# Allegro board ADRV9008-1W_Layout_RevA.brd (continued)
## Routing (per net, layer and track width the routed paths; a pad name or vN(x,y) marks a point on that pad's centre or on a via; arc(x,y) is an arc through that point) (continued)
VDD1P3_DIG: length 105.7
  TOP w0.203: R716.1 64.36,10.34 P904.1
  TOP w0.254: v4(37.24,35.68) U101.L9 v4(37.24,34.88) U101.L8 v4(37.24,34.08)
  TOP w0.508: R923.2 80.14,6.39 78.97,5.22 71.64,5.22 v2(70.65,6.21) v2(69.76,6.21) v2(68.87,6.21) v2(67.98,6.21) v2(67.98,6.97) v2(68.87,6.97) v2(69.76,6.97) v2(70.65,6.97)
  TOP w1.27: C951.1 68.02,9.57 P904.1
  L5_SIG w0.508: 64.04,9.57 P904.1 ; P904.1 65.12,8.49 ; P904.1 65.12,10.65 ; P904.1 66.2,9.57
  L5_SIG w1.905: 63.57,9.51 62.86,10.22 55.54,10.22 54.11,11.65 54.11,19.71 v2(52.42,21.4) v2(52.42,22.31) v2(53.47,22.31)
  L8_SIG w0.508: 65.12,8.49 P904.1 ; P904.1 66.2,9.57 ; P904.1 64.04,9.57 ; P904.1 65.12,10.65
  L12_PWR w0.635: v4(37.24,34.88) v4(37.24,35.68)
  L12_PWR w1.016: v4(37.24,34.88) v4(37.24,34.08) 38.25,33.07 40.27,33.07
  L12_PWR w1.27: 48.9,27.61 48.9,29.51 46.23,32.18 41.16,32.18 40.27,33.07
  L12_PWR w1.905: 48.9,27.61 50.17,26.34 50.17,24.8 52.66,22.31 ; 52.66,22.31 v2(52.42,22.31) v2(52.42,21.4) 53.46,21.4 v2(53.47,21.42) v2(53.47,22.31) 52.66,22.31
  BOTTOM w0.305: 37.24,34.46 v4(37.24,34.08) ; 37.24,34.46 v4(37.24,34.88) v4(37.24,35.68) 37.1,35.54 C643.1 ; 37.24,34.46 C642.1
  BOTTOM w0.508: 65.12,8.49 P904.1 ; P904.1 66.2,9.57 ; P904.1 64.04,9.57 ; P904.1 65.12,10.65
  BOTTOM w0.762: P904.1 64.99,9.44 C640.1
VDD_IF_LDO: length 2.9
  TOP w0.254: U902.5 57.63,1.99 58.1,2.46 58.1,3.62
  TOP w0.305: U902.7 56.66,3.36
VDD_INTERFACE: length 233.6
  TOP w0.203: R102.1 92.59,45.57 94.19,45.57 v2(94.81,44.94) ; U402.8 117.21,48.14 v2(117.49,47.87) ; v2(100.09,39.42) 100.09,39.42 C425.1
  TOP w0.254: U101.M12 v4(38.04,38.08)
  TOP w0.305: v2(122.74,53.6) U403.8 ; R104.1 93.34,36.75 98.32,36.75 100.09,38.52 v2(100.09,39.42) 100.09,39.99 R108.1 ; U902.2 51.35,3.29 51.03,3.61 ; R106.1 v2(94.81,44.94) ; U403.1 118.84,48.52 118.19,47.87 v2(117.49,47.87) ; v2(122.3,20.87) 122.11,21.06 U404.1 120.98,21.06 120.51,21.54 120.51,21.87 120.01,22.36 U404.4 ; v2(56.78,11.86) 55.25,13.39 R718.1 ; R832.1 R833.1 137.92,40.34 v4(137.83,40.26) ; R939.2 50.3,3.95 ; U902.1 51.41,3.94 51.01,4.35
  TOP w0.394: v4(132.75,12.32) 132.75,12.32 R111.1 ; P701.1 v2(60.2,66.02)
  TOP w0.508: P907.1 46.98,3.71 ; P907.1 48.06,2.63 ; P907.1 45.9,2.63 ; P907.1 46.98,1.55
  TOP w0.762: R938.2 131.45,9.75 v2(131.48,9.78)
  L3_PWR w0.508: v2(100.09,39.42) 100.09,41.5 100.21,41.62 100.21,42.15 99.83,42.52 99.47,42.52 97.05,44.94 97.05,45.23 96.52,45.76 95.64,45.76 v2(94.81,44.94)
  L3_PWR w0.635: 122.94,16.17 124.59,16.17 127.19,13.57 131.5,13.57 v4(132.75,12.32) 132.75,11.05 v2(131.48,9.78) ; 122.94,16.17 119.83,16.17 118.91,15.26 95.23,15.26 93.51,16.97 85.83,16.97 85.37,17.42 80.03,17.42 v2(78.75,18.71) 77.87,18.71 v2(77.86,18.72) v2(77.1,18.72) ; 122.94,16.17 122.94,20.23 v2(122.3,20.87)
  L12_PWR w0.203: 56.78,9.95 v2(56.78,11.86)
  L12_PWR w0.508: 115.2,40.43 115.2,46.78 116.28,47.87 v2(117.49,47.87) ; 125.36,40.18 125.36,47.16 123.83,48.69 123.83,52.5 v2(122.74,53.6) ; 45.9,2.63 P907.1 ; P907.1 46.98,1.55 ; P907.1 46.98,3.71 ; P907.1 48.06,2.63
  L12_PWR w0.762: 78.5,45 78.5,45.89 76.97,47.42 72.65,47.42 71.38,48.69 71.38,52.36 68.2,55.54 66.93,55.54 66.04,56.43 66.04,59.35 64.26,61.13 64.26,61.95 v2(60.2,66.02) ; 76.08,42.97 75.2,43.85 49.15,43.85 45.53,40.24 43.63,40.24 41.47,38.08 v4(38.04,38.08)
  BOTTOM w0.305: v4(38.04,38.08) 38.57,38.61 R110.1
  BOTTOM w0.394: C421.2 122.07,20.63 v2(122.3,20.87) 122.3,21.76 123.19,22.65 123.19,25.19 v2(121.54,26.84) ; P801.J39 v4(132.75,12.32) ; C423.2 122.81,53.53 v2(122.74,53.6) ; P801.K40 v2(131.48,9.78)
  BOTTOM w0.762: 46.47,3.14 46.45,3.14 46.45,3.16 ; 46.47,3.14 P907.1 ; 46.47,3.14 46.45,3.16 ; 46.45,3.16 C934.2
VDDA1P3_ANLG: length 67.3
  TOP w0.305: R726.1 v2(44.45,16.41)
  TOP w0.394: R916.2 83.03,20.04
  TOP w0.508: 63.98,15.46 P903.1 ; P903.1 65.06,16.54 ; P903.1 77.6,15.46 82.18,20.04 83.03,20.04 ; P903.1 65.06,14.38 ; 57.79,14.77 TP601.1 ; TP601.1 58.8,15.79 ; TP601.1 59.82,14.77 ; TP601.1 58.8,13.76
  TOP w0.762: C950.1 68.14,15.29 65.23,15.29 P903.1 64.35,16.17 C602.1
  L8_SIG w0.508: 63.98,15.46 P903.1 ; P903.1 65.06,14.38 ; P903.1 66.14,15.46 ; P903.1 65.06,16.54 ; TP601.1 59.82,14.77 ; TP601.1 57.79,14.77 ; TP601.1 58.8,13.76 ; TP601.1 58.8,15.79
  BOTTOM w0.394: R604.1 28.7,14.02 v6(28.71,14.01) ; R605.1 v2(45.85,18.33)
  BOTTOM w0.508: v2(7.5,29.5) 7.5,30.39 R607.1 ; P903.1 66.14,15.46 ; P903.1 65.06,14.38 ; P903.1 65.06,16.54 ; P903.1 63.98,15.46 ; R609.1 v2(7.24,19.6) ; TP601.1 59.82,14.77 ; TP601.1 57.79,14.77 ; TP601.1 58.8,15.79 ; TP601.1 58.8,13.76 ; R601.1 v2(41.53,15.91) v2(41.53,15.15)
  BOTTOM w0.762: 59.73,16.97 59.73,17.6 60.07,17.95 ; 21.59,57.44 20.84,57.44 R610.1 ; 21.59,57.44 21.6,57.44 v2(21.6,57.44) 21.59,57.44 ; 6.99,48.93 R608.1 ; R606.1 22.23,16.49
  BOTTOM w1.016: 19.59,61.66 v8(18.69,60.76) ; 19.59,61.66 19.59,61.66 v8(19.64,61.71) ; 19.59,61.66 E602.1 ; 8.38,48.93 6.99,48.93 ; 8.38,48.93 v8(9.65,48.93) ; 8.38,48.93 8.38,48.94 v8(8.32,48.94)
  BOTTOM w1.143: 22.23,16.49 22.25,16.48 22.25,15.62 22.23,15.61 v2(22.23,15.53)
  vias: v2(49.66,18.33) v2(50.33,18.33) v2(61.35,15.03) v2(61.35,14.27) v2(62.24,15.03) v2(62.24,14.27) v2(63.13,15.03) v2(63.13,14.27)
VDDA1P3_AUX_SYNTH: length 32.2
  TOP w0.254: U101.G8 v5(34.04,34.88)
  L12_PWR w0.279: v6(28.08,40.28) 28.39,40.28 28.83,39.84 28.83,39.8 28.84,39.79 28.84,39.51 29.07,39.28 29.4,39.28 29.4,39.28 29.47,39.28 29.85,38.9 29.85,38.01 30.99,36.87 32.61,36.87 32.84,36.64 32.84,36.31 33.07,36.08 33.36,36.08 33.38,36.07 33.4,36.07 33.63,35.84 33.63,35.82 33.64,35.8 33.64,35.27 v5(34.04,34.88)
  L12_PWR w0.508: v6(28.08,40.28) 22.35,53.76 TP612.1
  BOTTOM w0.305: C633.1 28.07,40.29
  BOTTOM w0.508: 27.94,40.87 27.94,40.42 v6(28.08,40.28) ; 27.94,40.87 28,40.81 C633.1 ; 27.94,40.87 C631.1
  BOTTOM w0.762: 20.7,56.19 20.7,56.18 20.69,56.17 20.65,55.18 ; 20.7,56.19 20.7,56.17 20.65,56.12 20.65,55.18 ; 20.7,56.19 R610.2 ; 20.65,55.18 20.65,54.85 TP612.1
VDDA1P3_AUX_VCO_LDO: length 28.3
  TOP w0.254: v5(30.04,35.68) U101.C10
  L12_PWR w0.508: v6(27.19,33.83) 26.81,33.83 25.82,32.84 25.1,32.84 22.53,30.27 v6(19.24,30.27)
  BOTTOM w0.203: 13.97,30.39 13.98,30.41 C623.1 ; 30.06,35.7 v5(30.04,35.68) ; C622.1 29.5,35.7
  BOTTOM w0.394: 30.06,35.7 28.27,35.7 27.64,35.07 27.64,34.28 v6(27.19,33.83)
  BOTTOM w0.508: 8.64,30.9 8.64,30.41 R607.2 8.63,31.97 TP609.1 8.64,30.9 ; 8.64,30.9 9.65,30.9 10.16,30.39 11.33,30.39 ; 11.33,30.39 19.12,30.39 v6(19.24,30.27) ; 11.33,30.39 C621.1
VDDA1P3_BB: length 21.1
  TOP w0.254: v4(31.64,31.68) U101.E5
  BOTTOM w0.203: v4(31.64,31.68) 31.5,31.82 C604.1
  BOTTOM w0.508: R601.2 41.4,18.06 41.4,19.69 C603.1 41.4,19.76 TP603.1 40.62,22.66 40.62,23.54 39.87,24.3 39.81,24.3 39.25,24.86 39.11,24.86 38.69,25.28 38.69,25.42 37.84,26.28 37.46,26.28 37.34,26.39 37.15,26.39 36.36,27.18 33.78,27.18 32.7,28.25 32.7,28.68 31.94,29.44 31.94,30.33 31.38,30.9 C605.1 31.25,31.29 v4(31.64,31.68)
VDDA1P3_CLOCK_SYNTH: length 21.2
  TOP w0.254: v5(34.04,31.68) U101.G5
  L12_PWR w0.394: TP607.1 45.85,22.56 43.86,24.55 42.67,24.55 41,26.23 39.13,26.23 38.83,25.93 37.87,25.93 36.89,26.91 36.89,29.46 36.21,30.14 35.69,30.14 34.15,31.68 v5(34.04,31.68)
  BOTTOM w0.394: R605.2 TP607.1
  BOTTOM w0.508: C617.1 33.98,31.62 v5(34.04,31.68) 33.97,31.74 C616.1
VDDA1P3_CLOCK_VCO_LDO: length 17.2
  TOP w0.254: v4(38.84,28.48) U101.N1
  BOTTOM w0.203: C611.1 38.67,28.65 v4(38.84,28.48)
  BOTTOM w0.508: R603.2 50.04,20.49
  BOTTOM w0.635: C610.1 40.8,27.82 40.25,28.37 C612.1 38.94,28.37 v4(38.84,28.48)
  BOTTOM w1.016: 50.04,20.49 TP605.1 47.5,24.42 47.5,25.69 45.21,27.98 42.42,27.98 42.26,27.82 C610.1
VDDA1P3_RF_LO: length 16.4
  TOP w0.254: v4(30.04,34.08) U101.C8
  L12_PWR w0.635: v4(30.04,34.08) 29.99,34.08 29.37,34.7 28.82,35.46
  L12_PWR w0.762: v6(17.27,39.69) v6(17.27,38.98) v6(17.27,38.27) 21.96,38.27 25.75,36.46 28.82,35.46
  BOTTOM w0.508: C627.1 29.97,34.01 v4(30.04,34.08)
VDDA1P3_RF_SYNTH: length 35.5
  TOP w0.254: v5(34.04,34.08) U101.G7
  L12_PWR w0.203: v7(25.53,60.49) v7(25.02,60.49)
  L12_PWR w0.279: v7(25.53,60.49) 25.53,58.46 29.36,54.63 29.36,50.99 28.95,50.58 28.95,45.24 29.09,45.11 29.09,43.98 28.74,43.64 28.74,42.53 29.34,41.93 29.34,40.55 30.36,39.54 31.37,39.54 33.13,37.78 33.78,37.78 33.87,37.68 34.22,37.68 35.26,36.65 35.26,34.75 35.01,34.5 34.46,34.5 v5(34.04,34.08)
  BOTTOM w0.203: v7(25.53,60.49) v7(25.02,60.49)
  BOTTOM w0.508: v5(34.04,34.08) 34.04,34.07 C609.1
VDDA1P3_RF_VCO_LDO: length 31.3
  TOP w0.254: U101.C5 v1(30.04,31.68) ; v4(30.04,32.48) U101.C6
  L3_PWR w0.508: v4(30.04,32.48) v1(30.04,31.68)
  L12_PWR w0.508: v6(25.66,31.29) 22.01,27.63 v6(19.18,27.63)
  BOTTOM w0.305: C628.1 15.15,26.36 15.13,26.37 ; 29.09,32.61 C629.1 30.03,32.49 v4(30.04,32.48)
  BOTTOM w0.394: 29.09,32.61 C630.1 27.68,32.61 27.56,32.49 26.86,32.49 v6(25.66,31.29)
  BOTTOM w0.508: v6(19.18,27.63) 16.39,27.63 13.78,25.02 13.78,21.44 12.7,20.36 TP611.1 12.19,19.85 11.09,18.75 10.37,18.75 9.53,19.6 R609.2
VDDA1P3_RX: length 11.2
  TOP w0.254: v4(30.04,30.88) U101.C3
  BOTTOM w0.394: v4(30.04,30.88) 30.04,30.2 30.29,29.95 C620.1 ; C618.1 24.25,18.68 24.25,18.67
  BOTTOM w0.762: R606.2 23.28,17.7
  BOTTOM w1.143: v6(26.93,25.95) TP608.1 26.4,22.79 24.25,18.67 23.28,17.7
VDDA1P3_RX_RF: length 8.4
  TOP w0.254: U101.B1 v4(29.24,28.48)
  L12_PWR w0.394: v6(28.71,23.03) 28.1,23.64 28.1,24.2 28.71,24.81 v7(28.71,26.06)
  BOTTOM w0.305: 29.23,28.47 v4(29.24,28.48) 29.5,28.74 C615.1
  BOTTOM w0.394: R612.2 28.7,23.03 v6(28.71,23.03) ; 28.71,26.71 28.71,27.52 28.91,27.71 28.91,28.14 29.23,28.47 ; 28.71,26.71 C613.1 ; 28.71,26.71 v7(28.71,26.06)
  BOTTOM w0.508: C614.1 28.92,27.73 28.91,27.71
VDDA1P3_SER: length 38.1
  TOP w0.203: v1(38.84,38.08) U101.N12 ; v1(38.84,36.48) U101.N10 ; U101.P12 v1(39.58,38.01) ; v1(39.63,38.94) 39.63,38.87 U101.P13 ; U101.M13 v1(38.04,38.88) ; U101.M14 v1(37.24,38.88) ; v1(38.84,38.88) U101.N13 ; U101.P11 v1(39.62,37.35) ; v1(38.84,37.28) U101.N11 ; v1(39.64,39.68) U101.P14
  TOP w0.254: v4(39.64,35.68) U101.P9 ; U101.L13 v5(36.44,38.88) ; v4(39.64,34.08) U101.P8 v4(38.84,34.08) U101.N8 ; U101.L14 v5(37.24,39.68) ; v4(38.84,35.68) U101.N9
  BOTTOM w0.203: 40.2,33.8 40.2,33.81 C634.1
  BOTTOM w0.394: 40.2,32.89 40.2,32.86 C635.1
  BOTTOM w0.508: C635.1 40.28,32.81 ; 40.28,32.81 40.2,32.89 40.2,33.8 39.93,34.08 v4(39.64,34.08) v4(38.84,34.08) ; 40.28,32.81 40.92,32.17 46.23,32.17 48.64,29.76 50.69,29.76 51.36,29.09 53.9,29.09 56.52,26.47 56.52,23.11 56.52,23.1 TP613.1
  BOTTOM w1.016: E611.2 TP613.1
VDDA1P8_AN: length 20.1
  TOP w0.203: U101.E12 v1(31.64,38.08)
  TOP w0.279: C947.1 v3(26.48,41.06)
  TOP w0.305: v3(26.48,41.06) 26.3,40.88 C948.1
  TOP w0.394: v2(47.37,17.18) 47.39,17.17 R724.1
  TOP w0.508: 99.19,3.72 TP901.1 ; TP901.1 101.22,3.72 ; TP901.1 100.21,2.71 ; TP901.1 100.21,4.74
  L3_PWR w0.203: 30.45,39.06 30.45,39.25 30.67,39.25 30.68,39.26 31,39.26 31.26,39 31.26,38.72 31.64,38.34 v1(31.64,38.08) 31.38,38.08 31,38.46 30.72,38.46 30.46,38.72 30.46,39.03 30.47,39.04 30.45,39.06
  L3_PWR w0.394: 46.74,16.68 46.87,16.68 v2(47.37,17.18)
  L3_PWR w0.508: TP901.1 100.21,4.74 ; TP901.1 101.22,3.72 ; TP901.1 100.21,2.71 ; TP901.1 99.19,3.72 ; v3(26.48,41.06) 28.64,41.06 30.45,39.25
  vias: v2(101.6,4.74) v2(101.86,3.72)
VDDA1P8_BB: length 67.4
  TOP w0.254: v5(32.44,30.88) U101.E4
  TOP w0.394: R722.1 v2(49.47,17.18)
  L5_SIG w0.114: TP903.1 26.55,8.8 27.82,8.8 29.59,10.58 31.37,10.58 31.63,10.33 33.91,10.33 34.67,11.09 40.64,11.09 41.02,10.71 43.69,10.71 49.47,16.49 v2(49.47,17.18)
  L10_SIG w0.279: v5(32.44,30.88) 32.04,30.48 31.49,30.48 31.24,30.24 31.24,29.1 30.94,28.8
  L10_SIG w0.305: 30.94,28.8 30.5,28.8
  L10_SIG w0.394: 29.83,27.62 29.83,28.12 30.5,28.8
  L10_SIG w0.508: 25.02,8.04 25.02,15.28 26.86,17.12 26.86,18.52 28.44,20.1 28.44,23.29 27.94,23.79 27.94,25.73 29.83,27.62
  L10_SIG w0.762: TP903.1 25.02,7.28 25.02,8.04
  BOTTOM w0.305: C944.1 32.51,30.95 v5(32.44,30.88) ; 25.61,5.75 R942.2
  BOTTOM w0.508: C945.1 32.58,30.73 v5(32.44,30.88)
  BOTTOM w1.016: 25.61,5.75 25.02,5.75 24.35,6.43 ; 24.35,6.43 C943.1 ; 24.35,6.43 TP903.1 24.26,8.55 C942.1
VDDA_1P8: length 113.1
  TOP w0.508: R931.2 102.34,6.62 v2(103.38,5.58) v2(104.14,5.58) v2(104.9,5.58) ; P906.1 107.64,4.74 ; P906.1 105.48,4.74 ; P906.1 106.56,3.66 ; P906.1 106.56,5.82
  BOTTOM w0.305: 27.05,5.75 R942.1 ; C940.2 105.54,3.72 P906.1 107.7,3.6 C941.2
  BOTTOM w0.508: P906.1 107.64,4.74 ; P906.1 105.48,4.74 ; P906.1 106.56,3.66 ; P906.1 106.56,5.82
  BOTTOM w1.016: 104.14,2.83 102.49,1.18 61.09,1.18 59.82,2.45 58.04,2.45 54.23,6.26 42.42,6.26 39.88,8.8 38.48,8.8 34.67,12.61 30.23,12.61 28.7,11.09 28.7,6.52 27.94,5.75 27.05,5.75
VDDA_3P3: length 139.8
  TOP w0.254: U101.C12 v1(30.04,38.08)
  TOP w0.394: v4(133.42,62.28) R848.1 ; R720.1 v3(51.56,17.18)
  TOP w0.508: R935.1 103.04,17.69 v2(103.04,19.29) v2(102.27,19.29) v2(101.51,19.29) 99.61,19.29 98.73,20.17 R927.2
  L3_PWR w0.203: 31.22,37.43 31.22,37.12 31.21,37.11 31.21,36.89 31.02,36.89 31.01,36.9 31,36.89 30.68,36.89 30.42,37.16 30.42,37.44 30.04,37.82 v1(30.04,38.08) 30.29,38.08 30.67,37.69 30.96,37.69 31.22,37.43
  L3_PWR w0.508: 45.72,58.71 47.75,58.71 49.15,57.32 51.82,57.32 v2(52.2,57.7) ; 45.72,58.71 45.72,59.86 44.33,61.25 v2(44.33,62.14) ; 45.72,58.71 43.44,58.71 v2(41.53,60.62) ; 45.72,58.71 45.72,56.3 ; 103.37,20.34 P905.1 ; P905.1 103.37,22.5 ; P905.1 104.45,21.42 ; P905.1 102.29,21.42 ; 34.04,39.66 32.51,38.14 32.51,37.38 31.88,36.74 31.36,36.74 31.21,36.89
  L10_SIG w0.203: 59.06,10.71 57.02,12.75 56,12.75 v3(51.56,17.18)
  L12_PWR w0.394: v4(133.42,62.28) 134.87,62.28 139.76,57.39 139.76,54.48 140.99,53.25 140.99,32.06 138.36,29.43 136.31,29.43 134.63,27.75 134.63,27.31 134.27,26.96 133.84,26.96 129.57,22.69 122.27,22.69 120.53,24.43 115.07,24.43 114.46,23.82 111.28,23.82 106.76,19.29 v2(103.04,19.29) v2(102.27,19.29) v2(101.51,19.29)
  BOTTOM w0.305: R119.1 v2(41.53,60.62) ; v2(52.2,57.7) 52.39,57.89 R120.1 ; C135.1 v2(44.33,62.14)
  BOTTOM w0.508: P905.1 103.37,22.5 ; P905.1 103.37,20.34 ; P905.1 102.29,21.42 ; P905.1 104.45,21.42 ; 44.33,61.32 v2(44.33,62.14)
  vias: v2(57.41,8.68) v2(58.43,8.68) v2(58.47,7.41) v2(58.94,8.05) v2(59.45,8.68) v2(59.45,7.41)
1P3_BUCK_OUT: length 25.4
  L8_SIG w0.394: v2(77.64,6.69) v2(76.87,6.69) v2(76.11,6.69) 75.41,7.4 75.41,18.42 77.23,20.24 84.4,20.24 v2(85.18,21.02)
  BOTTOM w0.394: v2(85.18,21.02) 85.59,20.61 R905.1
3P3V_CLK1: length 38.3
  TOP w0.203: v2(107.63,66.77) 107.12,66.77 C440.2 ; U404.6 119.82,20.88 v2(119.82,20.13)
  TOP w0.305: C424.2 117.74,55.17 v2(118.11,55.54) 118.53,55.54 118.84,55.23 U403.14
  TOP w0.394: v2(87.54,65.06) 87.38,64.9 87.38,64.86 C438.2 ; C442.2 85.71,61.57 v2(85.14,62.14) ; C439.2 86.31,64.8 v2(86.04,65.06) ; v2(88.87,56.77) 88.87,57.43 C427.2 ; v2(95.34,56.63) C429.2 ; v2(93.44,59.63) 92.84,59.03 C431.2 ; C428.2 v2(93.54,54.83) ; v2(85.14,60.63) 85.47,60.3 C418.1 ; C433.2 92.97,62.63 v2(93.45,62.63) ; C436.2 90.27,64.8 v2(90.54,65.06) ; C437.2 88.77,64.8 v2(89.04,65.06) ; C426.1 86.11,57.39 v2(86.11,56.73) ; v2(92.04,65.06) 91.77,64.8 C435.2 ; v2(93.41,66.78) 93.41,67.17 C434.2 ; v2(85.14,63.63) 85.93,62.84 C443.2 ; C444.2 v2(83.24,65.13) ; C441.2 83.31,57.16 v2(83.2,57.05) ; v2(93.42,61.13) 92.76,60.47 C432.2 ; C430.2 93.07,57.76 v2(93.44,58.13)
  BOTTOM w0.203: U401.69 v2(93.44,58.13) ; U401.66 v2(93.44,59.63) ; U401.39 v2(86.04,65.06) ; 94.24,56.63 U401.72 ; U401.1 v2(93.54,54.83) ; v2(86.11,56.73) 86.04,56.73 U401.16 ; U405.5 v2(107.63,66.77) ; 89.04,55.93 U401.10 ; 92.04,65.07 U401.51 ; U401.48 v2(90.54,65.06)
  BOTTOM w0.254: U401.60 v2(93.45,62.63) ; v2(93.42,61.13) 93.42,61.13 93.42,61.13 93.42,61.13 U401.63 ; 89.04,55.93 89.04,56.54 88.84,56.75 88.84,56.85 88.87,56.85 v2(88.87,56.77) ; U401.33 v2(85.14,63.63) ; v2(85.14,62.14) 85.03,62.14 85.03,62.08 84.98,62.13 U401.30 ; U401.45 v2(89.04,65.06) ; v2(93.41,66.78) 93.41,66.91 93.54,66.78 U401.54 ; U401.36 v2(83.24,65.13) ; v2(92.04,65.06) 92.04,65.07 ; v2(95.34,56.63) 94.24,56.63 ; U401.27 v2(85.14,60.63) ; U401.20 83.82,57.13 83.8,57.11 83.72,57.11 83.66,57.05 v2(83.2,57.05) ; U401.42 v2(87.54,65.06)
  BOTTOM w0.394: C422.2 v2(119.82,20.13) ; v2(83.2,57.05) 82.98,56.83 R440.1
  vias: v2(109.99,19.03) v2(109.99,18.27) v2(110.88,19.03) v2(110.88,18.27) v2(111.77,19.03) v2(111.77,18.27)
3P3V_VCXO: length 64.1
  BOTTOM w0.305: C938.2 127.01,62.26 127.01,62.27
  BOTTOM w0.394: C407.2 v2(111,63.8) Y402.6 Y401.6
  BOTTOM w0.508: E906.2 103.91,25.59 107.97,25.59 109.86,27.48 111.13,27.48 114.18,30.53 116.21,30.53 118.75,33.07 120.53,33.07 126.5,39.04 126.97,39.04 130.06,42.13 130.06,59.74 127.53,62.27 v2(126.23,62.27) v2(125.56,62.27) 125.56,61.43 124.82,60.69 124.35,60.21 R408.1
3P3VAUX: length 104.4
  TOP w0.305: 126.61,19.28 125.11,19.28 ; 126.61,19.28 C703.1 ; 126.61,19.28 127.66,19.28 v2(127.68,19.26) ; 125.11,19.28 123.44,19.28 U702.8 ; 125.11,19.28 C704.1 ; U703.10 v2(45.49,9.59) ; v2(112.97,20.97) 113.21,20.73 R708.2 ; U703.17 U703.16 ; R709.2 v2(113.8,17.83) ; R710.2 v2(113.8,16.05)
  TOP w0.635: U703.16 50.55,9.59 51.2,8.94 v8(51.2,7.67)
  L10_SIG w0.394: v2(45.49,9.59) 46.4,8.68 50.18,8.68 v8(51.2,7.67)
  L10_SIG w0.762: v2(112.97,20.97) 113.8,20.13 v2(113.8,17.83) v2(113.8,16.05) 113.8,4.75 110.12,1.06 107.45,1.06 107.15,0.76 105.96,0.76 105.66,1.06 61.6,1.06 59.19,3.48 57.03,3.48 52.84,7.67 v8(51.2,7.67)
  BOTTOM w0.394: C701.2 50.22,8.37 50.91,7.67 v8(51.2,7.67) 51.19,7.68 C702.1 ; P801.D32 v4(139.1,21.21)
ADP5054_VREG: length 20.4
  TOP w0.394: R903.2 87.86,8.29 v2(88.25,8.68) 88.95,9.38 90.64,9.38 91.04,8.98 91.04,8.83 v2(91.07,8.8) 91.4,9.13 91.4,16.32 v2(89.62,18.1)
  BOTTOM w0.203: C902.2 89.7,18.17 v2(89.62,18.1) 89.03,17.5 ; U901.44 88.75,17.22 89.03,17.5 ; U901.45 89.25,17.28 89.03,17.5
  BOTTOM w0.254: U901.13 90.75,9.12 v2(91.07,8.8) ; U901.18 v2(88.25,8.68)
AUX_SYNTH_VTUNE: length 49.1
  TOP w0.203: J101.1 56.39,35.98 P104.6
  TOP w0.254: v1(39.64,28.48) U101.P1
  L5_SIG w0.114: v1(39.64,28.48) 39.25,28.86 37.33,28.86 36.58,29.61 36.34,29.61 35.17,30.78 35.17,31.02 34.91,31.28 34.76,31.28 34.5,31.54 34.5,39.05 34.74,39.28 34.74,42.39 36.25,43.91 36.68,43.91 36.98,44.21 36.98,44.64 37.91,45.57 44.42,45.57 44.68,45.31 45.27,45.31 45.85,45.89 51.31,45.89 55.12,42.08 55.12,40.11 P104.6
AUXADC_0: length 64.3
  TOP w0.254: U101.F3 v1(32.44,30.08)
  L8_SIG w0.114: v1(32.44,30.08) 32.1,30.41 32.1,32.46 32.77,33.14 32.77,33.32 33.15,33.69 33.33,33.69 33.65,34.01 33.65,34.24 33.9,34.49 34.2,34.49 34.5,34.79 34.5,35.06 34.78,35.34 34.98,35.34 35.3,35.66 35.3,36.62 35.5,36.81 35.78,36.81 36.1,37.14 36.1,37.42 36.3,37.61 38.85,37.61 39.24,38 39.24,38.15 39.44,38.35 39.72,38.35 39.8,38.27 40.98,38.27 43.28,40.56 44.74,40.56 48.92,44.74 68.8,44.74 72.35,48.3 79.19,48.3 79.89,49 79.89,50.97 P103.3
  BOTTOM w0.203: C131.1 81.09,52.3 P103.3
AUXADC_1: length 66.8
  TOP w0.254: U101.F4 v1(32.44,31.68)
  L7_SIG w0.114: v1(32.44,31.68) 32.44,32 32.1,32.34 32.1,33.29 31.65,33.74 31.5,33.74 31.24,33.99 31.24,34.95 30.98,35.21 30.79,35.21 30.48,35.52 30.48,38.2 30.83,38.54 30.98,38.54 31.17,38.74 31.17,38.89 31.63,39.34 31.78,39.34 31.97,39.54 31.97,39.69 32.2,39.92 32.3,40.01 32.72,40.01 32.83,40.13 32.83,41.63 36.32,45.12 37.47,45.12 40.77,48.43 46.74,48.43 47.69,47.47 63.63,47.47 64.65,48.49 79.95,48.49 81.16,49.7
  BOTTOM w0.203: 81.16,49.7 81.09,49.63 C132.1
AUXADC_2: length 84.2
  TOP w0.254: v1(32.44,36.48) U101.F11
  L5_SIG w0.114: P103.5 76.27,54.58 76.24,54.58 75.94,54.88 75.94,54.91 74.55,56.3 66.04,56.3 62.42,59.92 39.69,59.92 38.1,58.33 30.23,58.33 28.58,56.68 27.56,56.68 25.91,55.03 25.91,51.14 26.59,50.46 26.59,49.42 25.08,47.92 25.08,45.89 25.88,45.09 25.88,40.16 29.23,36.81 32.1,36.81 v1(32.44,36.48)
  BOTTOM w0.203: C133.1 78.55,52.3 P103.5
AUXADC_3: length 82.2
  TOP w0.203: U101.E11 v1(31.64,37.28)
  L5_SIG w0.114: 78.62,49.7 77.35,50.97 77.35,52.68 76.08,53.95 66.24,53.95 61.03,59.16 39.94,59.16 38.48,57.69 36.23,57.69 35.72,57.19 29.93,57.19 28.82,56.09 27.73,56.09 26.5,54.86 26.5,51.39 27.18,50.71 27.18,49.03 25.78,47.63 25.78,46.18 26.93,45.03 26.93,42.21 27.08,42.05 28.51,40.62 28.51,40.17 28.83,39.85 28.83,39.61 29.15,39.28 29.31,39.28 29.57,39.02 29.57,38.79 29.96,38.41 30.18,38.41 30.5,38.09 30.5,37.94 30.74,37.7 31.22,37.7 v1(31.64,37.28)
  BOTTOM w0.203: C134.1 78.55,49.63 78.62,49.7
CLK+: length 7.5
  BOTTOM w0.203: C403.2 93.54,50.77 92.72,50.77 ; 92.72,50.77 92.28,50.77 92.06,50.99 92.06,51.72 92.97,52.62 92.97,55.06 93.04,55.13 U401.2 ; 92.72,50.77 R406.1
CLK-: length 8.1
  BOTTOM w0.203: C405.2 93.54,50.42 92.72,50.42 ; R406.2 92.72,50.42 ; 92.72,50.42 92.13,50.42 91.7,50.85 91.7,51.86 92.61,52.77 92.61,55.06 92.54,55.13 U401.3
CLK_RESETB: length 109.9
  TOP w0.203: v2(120.18,22.92) 119.33,22.92 119.1,22.68 119.1,22.04 119.43,21.71 U404.5
  L7_SIG w0.114: v2(120.18,22.92) 120.75,22.35 121.29,22.35 121.3,22.35 130.27,22.35 131,23.09 134.02,23.09 134.83,23.9 134.83,23.94 135.44,24.56 135.49,24.56 135.76,24.83 135.76,24.87 136.81,25.92 136.86,25.92 137.1,26.16 137.1,26.21 137.64,26.75 137.69,26.75 138.87,27.94 138.87,28.55 142.25,31.92 142.25,46.91 141.94,47.22 137.82,47.22 137.68,47.07 134.72,47.07 132.09,49.7 127.39,49.7 125.23,51.86 105.79,51.86 105.28,51.35 93.8,51.35 92.59,52.55 86.97,52.55 86.9,52.62 86.87,52.62 83.45,56.03 v2(83.45,56.36)
  BOTTOM w0.203: U401.19 83.72,56.63 v2(83.45,56.36)
  BOTTOM w0.394: v2(83.45,56.36) 82.93,55.84 R440.2
CLK_SYSREF_REQUEST: length 36.4
  TOP w0.203: U403.13 v2(119.49,56.68)
  L7_SIG w0.114: v2(119.49,56.68) 118.05,56.68 117.67,57.06 109.6,57.06 109.22,56.68 100.46,56.68 97.73,59.41 v2(97.73,65.95)
  BOTTOM w0.254: v2(97.73,65.95) 96.65,64.87 96.27,64.87 95.53,64.13 U401.57 ; R441.2 97.73,66.59
  BOTTOM w0.394: 97.73,66.59 v2(97.73,65.95)
DIR_CLK+: length 12.7
  L10_SIG w0.091: v2(89.35,51.41) 88.65,51.41 88.42,51.18 88.42,50.06 88.51,49.96 90.84,49.96 91.34,50.47 95.3,50.47 95.63,50.79 v2(95.63,52.09)
  BOTTOM w0.203: C402.2 94.88,52.09 v2(95.63,52.09) ; R416.2 89.78,50.85 89.35,51.28 v2(89.35,51.41)
DIR_CLK-: length 12.8
  L10_SIG w0.091: v2(95.63,49.09) 95.63,49.95 95.36,50.21 91.45,50.21 90.95,49.71 88.4,49.71 88.16,49.95 88.16,51.14 87.89,51.41 v2(87.12,51.41)
  BOTTOM w0.203: v2(87.12,51.41) 87.12,51.16 86.76,50.79 R415.2 ; v2(95.63,49.09) 94.88,49.09 94.87,49.08 C404.2
EPROM_A0: length 115.9
  TOP w0.203: U703.11 47.52,8.19 v2(46.87,7.54)
  TOP w0.305: v2(119.89,18.21) 118.85,19.25 U702.1 116.61,19.25 115.77,20.09 R711.2 R708.1
  L8_SIG w0.114: v2(119.89,18.21) 119.39,18.21 114.31,13.13 102.5,13.13 94.18,4.81 84.65,4.81 83.58,3.73 57.67,3.73 52.34,9.06 48.39,9.06 v2(46.87,7.54)
  L10_SIG w0.114: v2(119.89,18.21) 124.08,14.02 136.53,14.02 137.37,14.85 137.37,15.05 139.72,17.4 v4(141.64,17.4)
  BOTTOM w0.394: P801.C34 v4(141.64,17.4)
EPROM_A1: length 115.8
  TOP w0.203: U703.13 48.52,7.92 v2(48.14,7.54)
  TOP w0.305: v2(118.85,18.39) 118.64,18.6 U702.2 116.46,18.6 116.11,18.95 R712.2 R709.1
  L8_SIG w0.114: v2(48.14,7.54) 49.14,8.54 52.09,8.54 57.61,3.03 95.7,3.03 97.67,4.99 99.19,4.99 105.8,11.6 114.06,11.6 120.46,18.01 120.46,18.41 120.02,18.84 119.26,18.84 118.85,18.43 v2(118.85,18.39)
  L10_SIG w0.114: v2(118.85,18.39) 123.98,13.25 137.5,13.25 v4(140.37,16.13)
  BOTTOM w0.394: P801.D35 v4(140.37,16.13)
EPROM_A2: length 4.1
  TOP w0.305: R710.1 R713.2 115.63,17.17 115.97,17.51 116.07,17.51 116.5,17.95 U702.3
FMC_CLK_RESETB: length 24.7
  TOP w0.305: U404.2 122.77,21.71 123.77,22.71 128.97,22.71 129.86,21.82 135.57,21.82 138.57,24.82 138.57,27.03 v4(140.37,28.83)
  BOTTOM w0.394: v4(140.37,28.83) P801.D26
FMC_SYSREF_REQUEST: length 46.4
  TOP w0.203: U403.2 v2(119.49,50.59)
  L8_SIG w0.114: v2(119.49,50.59) 121.74,48.33 125.84,48.33 126.86,49.35 129.4,49.35 132.77,45.97 139.13,45.97 141.18,43.92 141.18,43.88 142.25,42.81 142.25,36.37 141.16,35.29 141.16,31.4 141.16,31.4 141.16,30.93 141.16,30.93 141.16,27.08 v4(140.37,26.29)
  BOTTOM w0.394: v4(140.37,26.29) P801.D27
FMCA_SCL: length 107
  TOP w0.203: U703.15 49.52,8.06 v2(50.05,7.54)
  TOP w0.305: U702.6 122.19,17.95 v2(121.8,18.33)
  L8_SIG w0.114: v2(50.05,7.54) 51.57,6.02 53.73,6.02 57.41,2.33 95.37,2.33 95.76,1.94 102.24,1.94 103.63,3.34 107.95,3.34 113.54,8.93 113.54,9.82 120.91,17.19 120.91,17.45 v2(121.8,18.33)
  L10_SIG w0.114: v4(141.64,22.48) 141.06,21.89 133.87,21.89 130.69,18.71 122.68,18.71 122.31,18.33 v2(121.8,18.33)
  BOTTOM w0.394: v4(141.64,22.48) P801.C30
FMCA_SDA: length 110.4
  TOP w0.203: U703.14 v2(49.02,7.54)
  TOP w0.305: U702.5 v2(121.82,17.3)
  L8_SIG w0.114: v2(49.02,7.54) 49.02,6.15 53.6,1.57 95,1.57 95.77,0.8 107.44,0.8 114.68,8.04 114.68,10.07 121.82,17.21 v2(121.82,17.3)
  L10_SIG w0.114: v2(121.82,17.3) 123.98,17.3 125.1,16.18 126.88,16.18 127.52,16.81 137.3,16.81 141.64,21.16 v4(141.64,21.21)
  BOTTOM w0.394: v4(141.64,21.21) P801.C31
FMCA_VADJ: length 13.2
  TOP w0.762: TP814.1 129.45,6.74 131.44,6.74 ; R938.1 131.44,6.74 ; 131.44,6.74 131.45,6.73 C932.1
  L12_PWR w0.508: TP814.1 129.31,7.89 ; TP814.1 128.3,6.87 ; TP814.1 127.28,7.89 ; TP814.1 128.3,8.91
  BOTTOM w0.394: P801.E39 v4(139.1,11.05) ; P801.G39 v4(136.56,11.05) ; P801.H40 v4(134.02,11.05) ; P801.F40 v4(137.83,9.78)
FMCA_VCC_3P3V: length 7.7
  L12_PWR w0.508: TP818.1 128.37,12.21 ; TP818.1 129.39,11.19 ; TP818.1 127.36,11.19 ; TP818.1 128.37,10.17
  BOTTOM w0.394: P801.D38 v4(140.37,12.32) ; P801.C39 v4(141.64,11.05) ; P801.D40 v4(140.37,9.78) ; P801.D36 v4(140.37,14.86)
FMCA_VCC_12P0V: length 5.9
  TOP w0.508: 121.29,12.87 TP819.1 ; TP819.1 121.29,14.91 ; TP819.1 120.28,13.89 ; TP819.1 122.31,13.89
  BOTTOM w0.394: P801.C35 v4(141.64,16.13) ; P801.C37 v4(141.64,13.59)
FPGA_REF_CLK+: length 49
  TOP w0.203: C803.1 141.01,56.26 140.5,56.77 v4(140.37,56.77)
  L7_SIG w0.091: v4(140.37,56.77) 140.25,56.77 139.99,57.03 139.99,57.41 132.84,64.56 127.36,64.56 126.22,65.7 110.26,65.7 109.45,64.89 108.33,64.89 v2(108.05,65.17)
  BOTTOM w0.203: v2(108.05,65.17) 107.82,64.94 106.43,64.94 102.03,60.53 99.72,60.53 99.59,60.54 99.25,60.88 98.85,60.88 R420.2
FPGA_REF_CLK-: length 49
  TOP w0.203: v4(139.1,56.77) 138.78,56.77 138.5,56.49 C804.1
  L7_SIG w0.091: v4(139.1,56.77) 139.65,56.77 139.74,56.86 139.74,57.3 132.74,64.3 127.26,64.3 126.11,65.44 110.37,65.44 109.55,64.63 108.33,64.63 v2(108.05,64.36)
  BOTTOM w0.203: R419.2 99.25,59.85 99.58,60.18 99.72,60.18 102.17,60.18 106.58,64.58 107.82,64.58 v2(108.05,64.36)
FPGA_SYSREF+: length 44.5
  TOP w0.203: v4(135.29,55.5) 134.86,55.07 134.86,54.66 135.13,54.66 135.13,54.25 134.86,54.25 134.86,53.01 135.06,52.81 R818.1
  L7_SIG w0.091: v2(99.68,63.79) 99.96,63.51 101.12,63.51 103.25,61.38 129.8,61.38 134.81,56.36 134.81,55.73 135.04,55.5 v4(135.29,55.5)
  BOTTOM w0.203: v2(99.68,63.79) 99.45,63.56 99.15,63.56 R424.2
FPGA_SYSREF-: length 44.5
  TOP w0.203: v4(134.02,55.5) 134.51,55.02 134.51,52.86 135.58,51.79 R819.1
  L7_SIG w0.091: v4(134.02,55.5) 134.33,55.5 134.56,55.73 134.56,56.26 129.69,61.13 103.15,61.13 101.01,63.26 99.96,63.26 v2(99.68,62.98)
  BOTTOM w0.203: R425.2 99.16,63.21 99.45,63.21 v2(99.68,62.98)
FPGA_SYSREF_OUT+: length 46.5
  TOP w0.203: R834.1 139.64,51.15 v4(139.1,51.69)
  L7_SIG w0.091: v4(139.1,51.69) 138.6,51.18 136.31,51.18 135,52.49 132.21,52.49 127,57.7 122.3,57.7 121.41,58.59 101.01,58.59 v2(100.74,58.85)
  BOTTOM w0.203: R451.1 98.01,57.82 98.27,57.57 99.13,57.57 100.16,58.6 100.48,58.6 v2(100.74,58.85)
FPGA_SYSREF_OUT-: length 46.5
  TOP w0.203: v4(139.1,50.42) 139.13,50.39 R835.1
  L7_SIG w0.091: v2(100.74,58.09) 100.98,58.33 121.31,58.33 122.2,57.44 126.9,57.44 132.1,52.24 134.9,52.24 136.21,50.93 139.1,50.93 139.29,50.74 139.29,50.61 v4(139.1,50.42)
  BOTTOM w0.203: R452.1 98.01,56.87 98.35,57.22 99.28,57.22 100.31,58.24 100.59,58.24 v2(100.74,58.09)
GP_INTERRUPT: length 113.9
  TOP w0.254: U101.J5 v1(35.64,32.48)
  TOP w0.394: R805.1 129.63,47.21 TP804.1
  L7_SIG w0.114: v1(35.64,32.48) 35.97,32.14 37.38,32.14 37.7,32.46 37.7,32.62 37.9,32.81 38.18,32.81 38.37,32.62 38.37,32.46 38.7,32.14 40.14,32.14 40.14,32.14 44.23,32.14 45.74,30.63 51.98,30.63 52.53,30.08 54.93,30.08 55.15,29.85 77.19,29.85 77.88,30.55 77.88,30.58 78.19,30.88 78.22,30.88 82.34,35.01 82.34,39.26 83.25,40.17 84.2,40.17 84.89,40.85 84.89,42.03 86.9,44.05 100.4,44.05 103.76,40.68 123,40.68 127.72,45.4 TP804.1
GPIO_0: length 116.9
  TOP w0.203: v4(132.75,37.72) 132.78,37.7 R808.1
  TOP w0.254: U101.K8 v1(36.44,34.08)
  TOP w0.305: P101.4 95.2,40.18 98.62,40.18 ; 98.62,40.18 R108.2 ; 98.62,40.18 98.62,39.67 R109.1
  L7_SIG w0.114: v4(132.75,37.72) 132.71,37.76 129.34,37.76 129.07,37.5 126.95,37.5 126.81,37.64 95.07,37.64 P101.4
  L8_SIG w0.097: 39.76,33.68 39.41,33.68
  L8_SIG w0.114: v1(36.44,34.08) 36.83,33.68 39.41,33.68 ; 39.76,33.68 39.78,33.68 40.17,33.29 43.14,33.29 43.44,33 46.99,33 48.58,34.58 49.98,34.58 50.29,34.27 51.06,34.27 51.56,34.77 59.37,34.77 60.01,35.41 75.57,35.41 77.35,37.19 77.35,39.47 77.85,39.98 83.89,39.98 84.97,41.06 84.97,42.01 85.54,42.58 90.74,42.58 91.38,43.22 94.24,43.22 95.13,42.33 95.13,40.11 P101.4
GPIO_1: length 129.8
  TOP w0.203: R809.1 132.78,36.43 v4(132.75,36.45)
  TOP w0.254: U101.J8 v1(35.64,34.88)
  TOP w0.305: P101.3 93.52,41.73 R107.1 R106.2
  L7_SIG w0.114: P101.3 93.86,40.43 92.78,39.35 92.78,39.33 92.75,39.31 92.75,38.1 94.24,36.61 117.63,36.61 117.64,36.62 130.91,36.62 131.09,36.45 v4(132.75,36.45)
  L8_SIG w0.114: v1(35.64,34.88) 35.35,34.88 34.93,34.46 34.75,34.46 34.37,34.09 34.37,33.94 32.9,32.46 32.9,30.74 33.23,30.41 33.38,30.41 33.57,30.22 33.57,30.06 34.03,29.61 34.18,29.61 34.37,29.42 34.37,29.26 34.7,28.94 36.78,28.94 37.6,28.11 40.14,28.11 42.05,26.2 43.45,26.2 45.04,24.61 54.29,24.61 54.49,24.81 58.56,24.81 59.32,25.57 85.86,25.57 90.56,30.27 90.56,30.78 91.77,31.99 91.77,35.54 92.62,36.39 92.62,40.14 P101.3
GPIO_2: length 124.6
  TOP w0.203: R822.1 135.79,38.49 v4(135.29,38.99)
  TOP w0.254: U101.J7 v1(34.84,33.28)
  TOP w0.305: R105.1 91.51,36.62 R104.2
  TOP w0.394: R105.1 91.46,38.71 P101.6
  L7_SIG w0.114: P101.6 92.59,40.11 92.59,41.76 93.41,42.58 97.92,42.58 102.27,38.24 126.21,38.24 126.5,38.53 129.81,38.53 130.21,38.94 130.66,38.94 131.2,38.4 134.71,38.4 v4(135.29,38.99)
  L8_SIG w0.114: P101.6 91.32,36.31 90.99,35.98 90.99,33.76 88.04,30.8 88.04,30.3 84.89,27.14 54.54,27.14 53.6,26.2 47.77,26.2 46.49,27.48 41.41,27.48 39.95,28.94 37.41,28.94 36.71,29.64 35.75,29.64 34.98,30.41 34.78,30.41 33.66,31.54 33.66,32.68 34.25,33.28 v1(34.84,33.28)
GPIO_3: length 124.5
  TOP w0.203: v4(132.75,35.18) 133.36,35.79 134.18,35.79 134.88,36.49 R823.1 ; R102.2 R103.1
  TOP w0.254: U101.K7 v1(36.44,33.28)
  TOP w0.305: R103.1 91.29,43.83 91.29,41.41 P101.5
  L7_SIG w0.114: v4(132.75,35.18) 132.54,34.96 119.26,34.96 118.68,34.39 116.16,34.39 115.72,34.83 92.91,34.83 90.21,37.53 90.21,40.27 P101.5
  L8_SIG w0.114: v1(36.44,33.28) 35.97,32.81 35.97,32.34 35.78,32.14 35.63,32.14 35.3,31.82 35.3,31.42 36.3,30.41 36.58,30.41 36.9,30.09 36.9,29.94 37.2,29.64 40.01,29.64 41.28,28.37 48.26,28.37 48.77,27.87 52.21,27.87 52.33,27.99 62.33,27.99 62.33,27.98 83.07,27.98 83.37,28.29 83.37,28.55 90.05,35.22 90.05,40.11 P101.5
GPIO_3P3_0: length 61.5
  TOP w0.254: U101.C1 29.49,27.93 v1(29.35,27.93)
  L8_SIG w0.114: v1(29.35,27.93) 29.24,27.93 28.81,28.36 28.81,34.92 29.23,35.34 29.38,35.34 29.39,35.35 29.4,35.35 29.7,35.66 29.7,35.82 29.9,36.01 30.09,36.01 31.3,37.22 31.3,37.42 31.5,37.61 31.66,37.61 33.54,39.49 33.54,44.01 34.23,44.7 34.23,47.47 35.56,48.8 35.56,49.47 35.86,49.77 36.24,49.77 38.01,51.55 38.01,51.83 39.31,53.13 46.48,53.13 46.87,53.51 48.52,53.51 48.64,53.38 49.98,53.38 50.36,53.76 65.04,53.76 P102.3
  BOTTOM w0.203: P102.3 C121.1
GPIO_3P3_1: length 54.5
  TOP w0.254: v1(31.2,28.31) 31.2,28.84 U101.D1
  L8_SIG w0.114: v1(31.2,28.31) 30.43,29.09 30.43,34.94 30.83,35.34 30.98,35.34 31.3,35.66 31.3,35.82 32.3,36.81 32.46,36.81 33.7,38.05 33.7,38.15 33.7,38.15 33.7,38.22 33.9,38.41 34.05,38.41 34.5,38.86 34.5,43.19 36.25,44.94 36.52,44.94 37.85,46.27 39.88,46.27 42.17,48.55 59.31,48.55 59.63,48.24 65.09,48.24 P102.4
  BOTTOM w0.203: P102.4 C122.1
GPIO_3P3_2: length 57.6
  TOP w0.254: U101.E1 v1(31.64,29.28)
  L8_SIG w0.114: v1(31.64,29.28) 31.25,29.66 31.25,31.52 31.25,31.52 31.25,34.16 32.18,35.09 32.9,35.09 33.14,35.34 33.38,35.34 33.66,35.62 33.66,35.77 34.03,36.14 34.18,36.14 34.37,36.34 34.37,36.57 34.71,36.9 34.96,36.9 35.3,37.24 35.3,42.45 36.99,44.14 36.99,44.23 38.26,45.51 43.5,45.51 45.91,47.92 48.2,47.92 48.45,47.66 66.23,47.66 67.76,49.19 67.76,50.33 67.12,50.97 65.29,50.97 P102.5
GPIO_3P3_3: length 52.1
  TOP w0.254: U101.C2 v1(30.04,29.28)
  L8_SIG w0.114: v1(30.04,29.28) 29.59,29.72 29.59,34.96 29.97,35.34 30.18,35.34 30.37,35.54 30.5,35.66 30.5,35.82 30.7,36.01 30.89,36.01 32.04,37.16 32.04,37.41 34.05,39.42 34.05,43.73 34.8,44.49 34.8,45.51 36.27,46.97 39.24,46.97 40.91,48.64 40.91,49.84 41.75,50.68 48.93,50.68 49.28,51.03 62.69,51.03 P102.6
GPIO_3P3_4: length 70.6
  TOP w0.254: U101.D2 v1(30.84,29.28)
  L7_SIG w0.114: v1(30.84,29.28) 30.43,29.69 30.43,30.24 30.2,30.46 29.9,30.46 29.59,30.77 29.59,31.8 29.28,32.11 28.77,32.11 27.16,33.72 27.16,35.62 26.23,36.55 26.23,40.55 25.85,40.93 25.85,48.11 26.61,48.87 26.61,55.67 29.66,58.71 39.44,58.71 40.07,59.35 42.46,59.35 48.42,53.38 60.34,53.38 P102.7
  BOTTOM w0.203: P102.7 C123.1
GPIO_3P3_5: length 64.2
  TOP w0.254: U101.E2 v1(31.64,30.08)
  L7_SIG w0.114: P102.8 61.48,49.39 60.52,48.43 48.77,48.43 47.18,50.01 45.66,50.01 41.85,53.82 40.26,53.82 39.14,54.94 34.76,54.94 34.73,54.96 34.31,54.96 34.01,54.67 30.31,54.67 29.59,53.95 29.59,51.22 29.02,50.65 29.02,44.81 29.85,43.97 29.85,42.56 29.47,42.18 29.47,40.17 29.57,40.06 29.57,34.86 29.9,34.54 30.27,34.54 30.48,34.33 30.48,33.31 31.17,32.62 31.17,32.46 31.57,32.06 31.8,32.06 32.03,31.84 32.03,30.46 v1(31.64,30.08)
  BOTTOM w0.203: P102.8 C124.1
GPIO_3P3_6: length 62.4
  TOP w0.254: U101.E3 v1(31.64,30.88)
  L7_SIG w0.114: P102.9 57.64,50.95 48.34,50.95 46.42,52.87 45.53,52.87 42.17,56.24 35.5,56.24 34.9,55.64 31.23,55.64 31.04,55.44 29.94,55.44 28.64,54.14 28.64,52.94 27.82,52.11 27.82,46.59 26.86,45.63 26.86,43.28 27.52,42.63 27.52,36.6 28.77,35.34 28.77,33.24 29.21,32.81 29.38,32.81 29.57,32.62 29.57,32.39 29.95,32.01 30.18,32.01 30.37,31.82 30.37,31.64 30.81,31.21 31.3,31.21 v1(31.64,30.88)
  BOTTOM w0.203: P102.9 C125.1
GPIO_3P3_7: length 38.1
  TOP w0.254: v1(31.64,38.88) U101.E13
  L5_SIG w0.114: P102.10 58.94,48.43 57.84,47.34 47.71,47.34 47.22,47.83 46.14,47.83 45.65,47.34 41.59,47.34 40.52,46.27 36.36,46.27 36.06,45.97 36.06,45.25 34.1,43.28 34.1,39.66 32.98,38.54 31.97,38.54 v1(31.64,38.88)
  BOTTOM w0.203: P102.10 C126.1
GPIO_3P3_8: length 55.1
  TOP w0.254: v1(30.84,38.88) U101.D13
  L5_SIG w0.114: v1(30.84,38.88) 31.21,39.25 33.02,39.25 33.53,39.76 33.53,44 33.74,44.21 33.74,44.57 36.13,46.97 40.01,46.97 41.47,48.43 57.1,48.43 57.66,49 57.66,50.98 P102.11
  L10_SIG w0.114: P102.11 54.88,53.76 52.83,53.76 47.69,58.9 v2(47.69,61.32)
  BOTTOM w0.203: U102.1 v2(47.69,61.32) ; P102.11 C127.1
GPIO_3P3_9: length 55.5
  TOP w0.203: C128.1 56.26,49.57 P102.12
  TOP w0.254: v1(30.04,38.88) U101.C13
  L5_SIG w0.114: P102.12 55.18,50.92 55.18,53.19 53.41,54.97 48.96,54.97 46.33,57.6 v2(42.01,57.6) 41.83,57.6 40.28,56.05 35.37,56.05 34.86,55.54 30.16,55.54 28.57,53.94 28.57,52.29 28.2,51.92 28.2,45.63 28.97,44.85 28.97,43.13 28.83,42.99 28.83,42.56 28.97,42.42 28.97,40.42 29.37,40.01 29.38,40.01 29.57,39.82 29.57,39.81 30.04,39.35 v1(30.04,38.88)
  BOTTOM w0.203: v2(42.01,57.6) 43.18,58.78 44.33,58.78
GPIO_3P3_10: length 46.4
  TOP w0.254: U101.D14 v1(30.84,39.68)
  L5_SIG w0.114: v1(30.84,39.68) 30.42,39.68 29.47,40.63 29.47,42.17 29.85,42.56 29.85,42.99 29.53,43.32 29.53,44.78 29.41,44.9 29.41,45.31 28.89,45.82 28.89,50.3 29.41,50.82 29.41,53.8 30.39,54.78 34.12,54.78 34.31,54.96 34.73,54.96 34.92,54.78 39.75,54.78 41.59,56.62 v2(44.33,56.62) 44.9,56.62 47.56,53.95 48.36,53.95 48.93,53.38 49.36,53.38 49.61,53.63 52.47,53.63 P102.13
  BOTTOM w0.203: P102.13 C129.1 ; v2(44.33,56.62) 44.33,57.51
GPIO_3P3_11: length 45.7
  TOP w0.203: C130.1 53.85,49.7 P102.14
  TOP w0.254: U101.E14 v1(31.64,39.68)
  L5_SIG w0.114: P102.14 52.66,50.9 50.61,50.9 50.1,51.41 48.45,51.41 47.06,52.81 47.06,53.63 45.09,55.6 v2(44.83,55.6) 43.88,55.6 41.53,53.25 39.37,53.25 37.59,51.47 37.59,51.09 36.71,50.2 36.29,50.2 35.56,49.47 35.56,49.06 32.7,46.2 32.7,40.28 32.43,40.01 32.3,40.01 31.96,39.68 v1(31.64,39.68)
  BOTTOM w0.203: U102.2 48.01,60.05 46.99,59.03 46.99,57.25 45.34,55.6 v2(44.83,55.6)
GPIO_4: length 113.1
  TOP w0.203: R707.2 88.78,37.01 88.78,37.02 P101.8 ; v4(132.75,30.1) 132.78,30.08 R812.1
  TOP w0.254: U101.K6 v1(36.44,32.48)
  L7_SIG w0.114: v4(132.75,30.1) 130.1,32.75 118.31,32.75 117.69,33.37 113.72,33.37 113.42,33.07 92.32,33.07 88.78,36.61 P101.8
  L8_SIG w0.114: P101.8 88.78,36.09 88.15,35.46 87.62,35.46 83.72,31.56 62.93,31.56 61.22,29.85 55.55,29.85 55.44,29.96 54.18,29.96 53.48,29.26 49.67,29.26 49.36,28.95 41.47,28.95 39.87,30.54 38.98,30.54 37.1,30.54 36.9,30.74 36.9,30.89 36.58,31.21 36.41,31.21 36.2,31.42 36.21,31.43 36.1,31.54 36.1,31.82 36.21,31.92 36.21,31.93 36.44,32.16 v1(36.44,32.48)
GPIO_5: length 63.2
  TOP w0.203: R813.1 89.91,43.67 R705.2
  TOP w0.254: U101.K5 v1(36.44,31.68)
  TOP w0.305: P101.7 88.82,41.42 R705.2
  L8_SIG w0.097: 39.89,31.29 39.51,31.29
  L8_SIG w0.114: P101.7 87.51,40.11 87.51,37.06 85.54,35.1 84.46,35.1 82.25,32.88 61.42,32.88 59.88,31.35 54.3,31.35 53.6,30.65 49.92,30.65 49.67,30.4 40.78,30.4 39.89,31.29 ; v1(36.44,31.68) 36.76,31.68 37.15,31.29 39.51,31.29
GPIO_6: length 120
  TOP w0.203: R843.1 141.67,33.93 v4(141.65,33.95)
  TOP w0.254: U101.L5 v1(37.24,31.68)
  TOP w0.305: P101.10 86.65,38.44 R706.2
  L7_SIG w0.114: v4(141.65,33.95) 141.11,34.49 141.11,35.06 137.03,39.14 137.03,39.18 135.27,40.93 125.03,40.93 124.03,39.93 123.27,39.93 123.22,39.98 102.94,39.98 99.63,43.28 88.97,43.28 87.51,41.82 87.51,40.11 P101.10
  L8_SIG w0.114: v1(37.24,31.68) 37.61,32.05 39.89,32.05 40.52,31.42 49.28,31.42 49.85,31.98 55.19,31.98 55.32,31.86 56.96,31.86 57.85,32.75 59.77,32.75 60.4,33.39 79.66,33.39 80.16,33.89 80.16,34.01 82.65,36.49 82.81,36.49 82.81,36.5 84.97,36.5 86.24,37.77 P101.10
GPIO_7: length 123.4
  TOP w0.203: v1(137.8,31.35) 138.69,31.35 139.26,31.92 R844.1
  TOP w0.254: U101.L6 v1(37.24,32.48)
  TOP w0.305: P101.9 86.23,41.4 86.23,43.62 R702.2
  L7_SIG w0.114: v1(137.8,31.35) 137.16,30.71 137.16,29.88 136.66,29.38 135.65,29.38 134.49,28.23 132.07,28.23 131.31,28.99 130.7,28.99 130.64,28.93 126.88,28.93 126.17,29.64 121.1,29.64 120.72,29.26 118.93,29.26 117.79,30.39 114.49,30.39 113.6,31.28 91.2,31.28 91.07,31.42 90.43,31.42 89.54,32.3 89.54,32.94 84.97,37.52 84.97,39.54 86.24,40.81 P101.9
  L8_SIG w0.114: P101.9 86.24,40.43 84.97,39.16 84.97,38.27 84.34,37.64 81.03,37.64 78.11,34.72 60.72,34.72 59.38,33.38 49.6,33.38 48.2,31.98 47.25,31.98 47.18,32.05 40.65,32.05 39.76,32.94 38.7,32.94 37.7,32.94 v1(37.24,32.48)
GPIO_8: length 131.5
  TOP w0.203: R827.1 136.18,29.72 v4(136.56,30.1)
  TOP w0.254: U101.L12 v1(37.24,38.08)
  L5_SIG w0.091: v4(136.56,30.1) 136.56,30.8 136.47,30.89 135.86,30.89 135.77,30.8 135.77,29.75 135.96,29.56 138.5,29.56 138.81,29.87 138.81,37.55 136.81,39.54 131.22,39.54 129.95,40.81 124.11,40.81 123.86,41.07 103.13,41.07 101.55,42.65 92.99,42.65 92.41,43.23 85.16,43.23 84.52,42.59 84.52,42.2 84.84,41.89 84.84,40.62 83.7,39.48 P101.12
  L10_SIG w0.091: v1(37.24,38.08) 37.42,38.26 37.42,38.33 37.56,38.47 37.56,39.81 37.37,40 37.1,40 37.05,40.06 37.05,41.04 38.08,42.08 42.74,42.08 43.37,42.71 48.14,42.71 48.83,43.41 55.56,43.41 56.27,42.7 67.41,42.7 73.44,36.67 82.73,36.67 83.7,37.64 P101.12
GPIO_9: length 123
  TOP w0.203: v4(134.02,33.91) 134.33,33.6 R810.1
  TOP w0.254: U101.K12 v1(36.44,38.08)
  L5_SIG w0.091: P101.11 82.55,40.24 82.55,38.44 83.25,37.75 84.16,37.75 84.17,37.76 84.22,37.76 84.89,38.42 84.89,39.41 85.72,40.24 101.58,40.24 102.15,39.66 124.06,39.66 129.27,34.46 131.38,34.46 132.44,33.4 133.93,33.4 134.02,33.49 v4(134.02,33.91)
  L10_SIG w0.091: P101.11 82.55,40.24 82.55,38.1 81.77,37.31 80.48,37.31 79.76,38.03 79.76,42.03 79.21,42.58 75.72,42.58 73.91,44.39 40.52,44.39 39.35,43.22 36.49,43.22 35.66,42.39 35.66,39.4 35.76,39.31 35.85,39.31 36.08,39.08 36.08,38.43 v1(36.44,38.08)
GPIO_10: length 123
  TOP w0.203: v4(134.02,32.64) 134.33,32.33 R811.1
  TOP w0.254: U101.J12 v1(35.64,38.08)
  L5_SIG w0.091: v4(134.02,32.64) 134.02,33.06 133.93,33.15 132.33,33.15 131.28,34.2 129.16,34.2 123.95,39.41 102.05,39.41 101.48,39.98 85.82,39.98 85.14,39.3 85.14,38.32 84.33,37.5 84.28,37.5 84.26,37.49 83.14,37.49 82.3,38.33 82.3,39.89 82.21,39.98 81.25,39.98 81.16,39.89 P101.14
  L10_SIG w0.091: P101.14 81.16,39.16 81.71,39.71 82.21,39.71 82.3,39.62 82.3,38.2 81.66,37.57 80.58,37.57 80.01,38.14 80.01,42.14 79.31,42.84 75.82,42.84 74.01,44.65 40.42,44.65 39.24,43.47 36.39,43.47 35.41,42.5 35.41,39.17 35.31,39.07 35.31,38.4 v1(35.64,38.08)
GPIO_11: length 117.2
  TOP w0.203: v4(135.29,35.18) 135.26,35.14 R824.1
  TOP w0.254: U101.H12 v1(34.84,38.08)
  L5_SIG w0.091: v4(135.29,35.18) 135.71,35.18 135.8,35.09 135.8,33.78 135.46,33.44 135.1,33.44 134.48,32.82 134.48,32.45 134.21,32.19 130.8,32.19 130.01,32.97 128.56,32.97 128.27,32.68 126.94,32.68 122.62,37 118.3,37 117.92,36.62 116.44,36.62 115.59,37.47 87.74,37.47 87.21,36.93 81.28,36.93 80.01,38.2 80.01,40.68 80.72,41.39 P101.13
  L7_SIG w0.091: v1(34.84,38.08) 35.07,38.31 35.21,38.45 44.02,38.45 45.85,40.28 62.74,40.28 65.62,43.16 79.01,43.16 80.04,42.12 80.04,40.97 80.27,40.74 80.52,40.74 P101.13
GPIO_12: length 116.8
  TOP w0.203: v4(136.56,35.18) 136.53,35.14 R825.1
  TOP w0.254: U101.H11 v1(34.84,37.28)
  L5_SIG w0.091: v4(136.56,35.18) 136.15,35.18 136.06,35.09 136.06,33.67 135.57,33.19 135.2,33.19 134.73,32.71 134.73,32.35 134.32,31.93 130.69,31.93 129.91,32.72 128.67,32.72 128.38,32.42 126.83,32.42 122.52,36.74 118.41,36.74 118.03,36.36 116.33,36.36 115.48,37.21 87.85,37.21 87.31,36.68 81.18,36.68 79.76,38.1 79.76,38.53 79.45,38.85 P101.16
  L7_SIG w0.091: v1(34.84,37.28) 35.25,37.69 39.71,37.69 39.92,37.89 39.92,38.06 40.06,38.2 44.13,38.2 45.96,40.02 62.85,40.02 65.72,42.9 78.9,42.9 79.79,42.02 79.79,40.9 78.62,39.73 P101.16
GPIO_13: length 121.4
  TOP w0.203: v4(135.29,42.8) 135.32,42.77 R831.1
  TOP w0.254: U101.J11 v1(35.64,37.28)
  L5_SIG w0.091: P101.15 77.52,40.29 75.3,40.29 74.98,40.61 74.98,41.84 75.63,42.49 75.64,42.49 76.31,43.16 76.88,43.16 78.47,44.74 92.14,44.74 92.82,44.06 102.93,44.06 104.66,42.34 114.69,42.34 116.59,44.24 124.71,44.24 125.22,43.73 131.62,43.73 132.5,44.62 135.38,44.62 135.75,44.26 135.75,43.88 135.39,43.53 135.39,42.9 v4(135.29,42.8)
  L7_SIG w0.091: P101.15 77.47,40.24 77.47,38.26 76.33,37.12 75.42,37.12 73.2,34.9 52.28,34.9 51.74,35.45 49.19,35.45 48.97,35.23 42.55,35.23 42.02,34.7 39.99,34.7 39.79,34.5 39.48,34.5 39.26,34.72 38.77,34.72 38.14,35.35 37.9,35.35 37.71,35.54 37.71,35.78 37.34,36.15 37.1,36.15 36.91,36.34 36.91,36.61 36.83,36.69 36.7,36.69 36.54,36.84 36.07,36.84 v1(35.64,37.28)
GPIO_14: length 121.4
  TOP w0.203: v4(136.56,42.8) 136.46,42.7 R830.1
  TOP w0.254: U101.K11 v1(36.44,37.28)
  L5_SIG w0.091: P101.18 77.16,38.85 77.35,39.03 77.35,39.79 77.1,40.03 75.2,40.03 74.73,40.5 74.73,41.95 75.52,42.74 75.53,42.74 76.2,43.41 76.77,43.41 78.36,45 92.25,45 92.93,44.32 103.04,44.32 104.76,42.59 114.58,42.59 116.49,44.5 124.81,44.5 125.32,43.99 131.52,43.99 132.4,44.87 135.49,44.87 136,44.36 136,43.78 135.64,43.42 135.64,43.09 135.93,42.8 v4(136.56,42.8)
  L7_SIG w0.091: v1(36.44,37.28) 36.47,37.28 36.8,36.94 36.94,36.94 37.08,36.8 37.37,36.8 37.56,36.61 37.56,36.29 37.85,36 38.17,36 38.36,35.81 38.36,35.49 38.88,34.97 39.2,34.97 39.48,35.25 39.79,35.25 40.1,34.95 41.92,34.95 42.45,35.48 48.86,35.48 49.09,35.7 51.84,35.7 52.39,35.16 73.09,35.16 75.31,37.38 76.23,37.38 77.22,38.37 77.22,39.23 77.12,39.33 76.57,39.33 P101.18
GPIO_15: length 131.8
  TOP w0.203: v4(135.29,30.1) 135.62,30.42 R826.1
  TOP w0.254: U101.L11 v1(37.24,37.28)
  L5_SIG w0.091: v4(135.29,30.1) 135.29,29.87 135.86,29.3 138.6,29.3 139.06,29.76 139.06,37.65 136.91,39.8 131.33,39.8 130.06,41.07 124.22,41.07 123.96,41.32 103.24,41.32 101.66,42.9 93.09,42.9 92.51,43.48 85.05,43.48 84.15,42.58 77.28,42.58 P101.17
  L10_SIG w0.091: v1(37.24,37.28) 36.88,37.28 36.79,37.37 36.79,41.15 37.98,42.33 42.63,42.33 43.27,42.97 48.03,42.97 48.73,43.66 55.67,43.66 56.38,42.96 67.51,42.96 73.48,36.99 74.71,36.99 74.81,37.08 74.81,41.59 75.05,41.83 75.64,41.83 P101.17
GPIO_16: length 115.5
  TOP w0.203: R817.1 141.64,48.84 v4(141.64,49.15)
  TOP w0.254: U101.M11 v1(38.04,37.28)
  L5_SIG w0.091: v4(141.64,49.15) 141.27,49.15 141.1,49.32 141.1,49.7 140.85,49.95 132.84,49.95 130.18,52.62 125.39,52.62 123.23,54.78 109.84,54.78 109.2,55.41 102.24,55.41 97.16,50.33 88.9,50.33 87.12,48.55 77.37,48.55 74.19,45.38 73.54,45.38 70.04,41.88 v1(69.67,41.88)
  L7_SIG w0.091: v1(38.04,37.28) 38.35,37.28 38.82,36.8 40.83,36.8 41.09,37.06 48.03,37.06 48.22,37.25 51.59,37.25 52.03,37.7 65.85,37.7 69.67,41.51 v1(69.67,41.88)
GPIO_17: length 115.4
  TOP w0.203: v4(140.37,49.15) 140.37,48.84 R816.1
  TOP w0.254: U101.M10 v1(38.04,36.48)
  L5_SIG w0.091: v4(140.37,49.15) 140.61,49.15 140.85,49.38 140.85,49.59 140.74,49.7 132.74,49.7 130.07,52.36 125.29,52.36 123.13,54.52 109.73,54.52 109.1,55.16 102.34,55.16 97.26,50.08 89.01,50.08 87.23,48.3 77.47,48.3 74.3,45.12 73.64,45.12 71.15,42.64 70.22,41.7 v1(70.22,41.33)
  L7_SIG w0.091: v1(38.04,36.48) 38.38,36.48 38.77,36.09 38.91,36.09 39.16,36.34 39.22,36.34 39.47,36.09 39.75,36.09 39.94,36.28 39.94,36.46 40.02,36.55 40.93,36.55 41.19,36.81 48.14,36.81 48.33,37 51.69,37 52.14,37.44 65.96,37.44 69.85,41.33 v1(70.22,41.33)
GPIO_18: length 34.6
  TOP w0.203: R113.1 58.99,36.42 58.99,35.29 R704.2
  TOP w0.254: U101.J3 v1(34.84,30.88)
  TOP w0.305: P104.4 58.99,38.77 R113.1
  L8_SIG w0.114: v1(34.84,30.88) 34.5,31.21 34.5,31.82 34.83,32.14 34.98,32.14 35.19,32.35 35.19,33.32 36.36,34.49 41.75,34.49 42.67,35.41 48.39,35.41 49.91,36.93 52.07,36.93 52.71,37.57 57.66,37.57 P104.4
  BOTTOM w0.203: R837.1 P104.4
INPUT_VOLTAGE: length 42
  TOP w0.203: CR901.C 121.36,5.44 DS901.A
  TOP w0.305: R714.2 v2(55.9,7.29)
  L7_SIG w0.114: v2(55.9,7.29) 56.41,6.78 60.21,6.78 62.37,4.62 80.18,4.62 v2(84.09,8.52)
  BOTTOM w0.254: 83.53,16.42 84.03,15.92 U901.36 ; 85.26,17.59 85.75,17.1 U901.38 ; v2(93.15,12.81) 92.8,13.17 v2(92.49,13.17) ; v2(85.59,8.5) 86.25,9.16 U901.22 ; U901.6 92.24,13.42 v2(92.49,13.17) ; v2(92.49,13.17) 92.24,12.92 U901.7
  BOTTOM w0.394: R909.1 v2(92.94,18.39)
  vias: v2(83.38,18.28) v2(83.71,16.73) v2(84.24,18.28) v2(84.57,16.73) v2(84.82,8.5) v2(98.77,13.32) v2(98.77,12.43) v2(98.77,11.57) v8(117.74,6.02) v8(117.74,4.3) v8(119.26,6.02) v8(119.26,4.3) v8(123.71,6.02) v8(123.71,4.3) v8(125.23,6.02) v8(125.23,4.3)
JTAG_TDI: length 1.6
  TOP w0.305: R840.2 140.04,22.15 v4(140.37,22.48)
  BOTTOM w0.394: v4(140.37,22.48) P801.D30
JTAG_TDO: length 1.6
  TOP w0.305: R840.1 140.07,21.51 v4(140.37,21.21)
  BOTTOM w0.394: v4(140.37,21.21) P801.D31
LDO_VCO_2P5: length 3.2
  BOTTOM w0.203: C416.1 86.25,54.23
  BOTTOM w0.254: C417.1 86.24,54.22 86.55,54.53 86.55,55.04 86.54,55.05 86.54,55.37 U401.15
LF_EXT_CAP: length 2.9
  BOTTOM w0.203: C414.2 90.11,53.81 R439.2
  BOTTOM w0.254: R439.2 90.54,54.29 90.54,55.18 U401.7
LF_PLL2: length 2.3
  BOTTOM w0.254: U401.14 87.04,54.82 87.25,54.61 87.25,53.85 87.24,53.86 C416.2
OUT1: length 3.9
  BOTTOM w0.203: R418.1 96.63,60.58 96.65,60.56 ; 96.65,60.56 96.97,60.56 97.16,60.56 97.47,60.87 R420.1 ; 96.65,60.56 95.11,60.56 95.04,60.63 U401.64
OUT1_N: length 4
  BOTTOM w0.203: R419.1 97.47,59.86 97.13,60.2 96.65,60.2 ; U401.65 95.04,60.13 95.11,60.2 96.65,60.2 ; 96.65,60.2 96.63,60.18 R418.2
OUT3: length 3.9
  BOTTOM w0.203: 96.72,63.56 R423.2 ; 96.72,63.56 97.57,63.56 R424.1 ; 96.72,63.56 95.16,63.56 95.09,63.63 94.47,63.63 U401.58
OUT3_N: length 3.9
  BOTTOM w0.203: U401.59 95.09,63.13 95.16,63.2 96.72,63.2 ; 96.72,63.2 97.57,63.2 R425.1 ; 96.72,63.2 R423.1
OUT5: length 19.1
  TOP w0.203: 91,66.78 90.93,66.84 v2(90.93,67.34) ; 91,66.78 R426.1 ; 91,66.78 91.11,66.66 91.11,66.14 91.52,65.72 94.21,65.72 95.25,64.68 103.25,64.68 103.66,65.09 105.22,65.09 105.42,64.89 105.42,64.65 105.16,64.38 C410.1
  BOTTOM w0.203: v2(90.93,67.34) 91.11,67.17 91.11,66.36 91.04,66.29 U401.49
OUT5_N: length 19.1
  TOP w0.203: C411.1 106.05,64.38 105.78,64.65 105.78,65.03 105.37,65.44 103.51,65.44 103.11,65.04 95.4,65.04 94.36,66.08 91.67,66.08 91.47,66.28 91.47,66.66 91.63,66.83 ; 91.63,66.83 91.63,66.82 R426.2 ; 91.63,66.83 91.65,66.84 v2(91.65,67.34)
  BOTTOM w0.203: U401.50 91.54,66.26 91.47,66.33 91.47,67.17 v2(91.65,67.34)
OUT7: length 13.9
  TOP w0.203: 87.95,66.83 87.93,66.84 v2(87.93,67.34) ; 87.95,66.83 R427.1 ; 87.95,66.83 88.11,66.66 88.11,66.28 87.91,66.08 85.92,66.08 85.35,66.65 80.13,66.65 79.82,66.97 78.91,66.97 78.5,66.56 78.5,66.21 C412.1
  BOTTOM w0.203: U401.43 88.04,66.26 88.11,66.33 88.11,67.17 v2(87.93,67.34)
OUT7_N: length 13.8
  TOP w0.203: 88.58,66.78 88.47,66.66 88.47,66.14 88.06,65.72 85.77,65.72 85.2,66.3 79.99,66.3 79.67,66.61 79.06,66.61 78.86,66.41 78.86,66.21 C413.1 ; 88.58,66.78 88.65,66.84 v2(88.65,67.34) ; 88.58,66.78 R427.2
  BOTTOM w0.203: v2(88.65,67.34) 88.47,67.17 88.47,66.36 88.54,66.29 U401.44
OUT8: length 22.7
  TOP w0.203: 85.73,67.76 86.57,67.76 86.79,67.53 86.79,67.16 86.66,67.04 86.66,66.95 86.55,66.84 v2(86.43,66.84) ; 85.73,67.76 R428.1 ; 85.73,67.76 70.86,67.76 70.58,67.48 70.18,67.48 69.9,67.76 69.49,67.76 68.75,67.01 68.75,66.61 68.87,66.49 69.45,66.49 69.59,66.35 69.59,66.06 R429.1
  BOTTOM w0.203: U401.40 86.54,66.26 86.61,66.33 86.61,66.66 v2(86.43,66.84)
OUT8_N: length 22.7
  TOP w0.203: 85.73,68.11 69.34,68.11 68.39,67.16 R430.1 ; 85.73,68.11 R428.2 ; 85.73,68.11 86.71,68.11 87.15,67.68 v2(87.15,66.84)
  BOTTOM w0.203: v2(87.15,66.84) 86.97,66.66 86.97,66.36 87.04,66.29 U401.41
OUT12: length 7.1
  BOTTOM w0.203: U401.28 83.54,61.13 83.47,61.2 82.7,61.2 82.26,61.65 82.26,63.33 82.03,63.56 80.57,63.56 ; 80.57,63.56 R431.2 ; 80.57,63.56 80.01,63.56 79.77,63.32 R432.1
